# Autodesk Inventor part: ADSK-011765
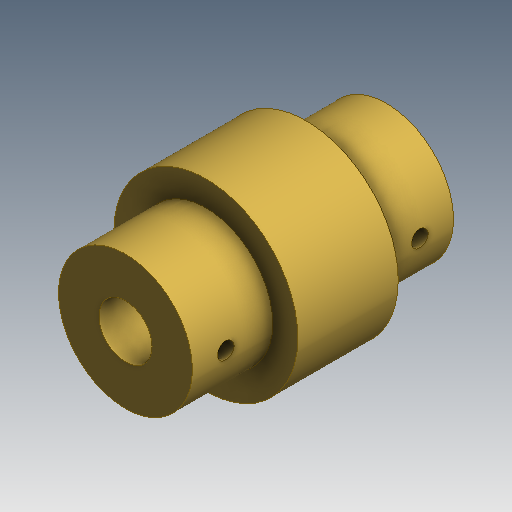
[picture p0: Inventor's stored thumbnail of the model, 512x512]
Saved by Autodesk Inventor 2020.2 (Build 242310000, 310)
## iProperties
Created: 1999-12
Part Number: ADSK-011765
Document SubType Name: Modeling
Designer: tgregory
Material: Générique
Density: 1 g/cm^3
Appearance: Vorgabe
Mass: 110.229 g
Surface Area: 210.674 cm^2
Volume: 110.229 cm^3
Control State: 0
Checked Out: False
Master: False
Shininess: 0.0
Length Units: 11272
Angle Units: 11279
Time Units: 11290
Mass Units: 11286
Length Display Precision: 3
Angle Display Precision: 2
Compacted: True
Dimensions: 2,2x3,1x2,2 in
Mass: 0,243 lb
VLT_Material: Generic
Density: 0.0
Volumn: 0.0
Area: 0.0
PropertySet Name: Model Information
Author: tgregory
Revision Number: -
Title: ADSK-011765
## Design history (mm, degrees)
node "Extrusion1" dims "d1" = 78.0034, "d2" = 0
node "Extrusion2" dims "d4" = 24.003, "d5" = 0
node "Extrusion3" dims "d7" = 24.003, "d8" = 0
node "Extrusion4" dims "d10" = 29.9974, "d11" = 0
node "Extrusion5" dims "d13" = 29.9974, "d14" = 0
node "Extrusion6" dims "d16" = 18.0086, "d17" = 0
workplane "Work Plane1"
node "Hole1" dims "d20" = 4.9784, "d21" = 9.525, "d22" = 6.35, "d23" = 60 deg, "d24" = 19.05, "d25" = 118 deg
node "Solide1"
node "Corps solides"
node "Corps surfaciques"
sketch "Sketch1"
  geometry: C1 r 27.495 at (0, 0)
  constraints: 1 centre point
  dimensions: "d0" = 54.991 diameter of C1
sketch "Sketch2"
  geometry: C1 r 27.495 at (0, 0) reference; C2 r 20.002 at (0, 0)
  constraints: 1 centre point, 1 coincident
  dimensions: "d3" = 40.005 diameter of C2
sketch "Sketch3"
  geometry: C1 r 27.495 at (0, 0) reference; C2 r 20.002 at (0, 0)
  constraints: 1 centre point, 1 coincident
  dimensions: "d6" = 40.005 diameter of C2
sketch "Sketch4"
  geometry: C1 r 20.002 at (0, 0) reference; C2 r 7.938 at (0, 0)
  constraints: 1 centre point, 1 coincident
  dimensions: "d9" = 15.875 diameter of C2
sketch "Sketch5"
  geometry: C1 r 20.002 at (0, 0) reference; C2 r 7 at (0, 0)
  constraints: 1 centre point, 1 coincident
  dimensions: "d12" = 14.00048 diameter of C2
sketch "Sketch6"
  geometry: C1 r 7 at (0, 0) reference; C2 r 13.5 at (0, 0)
  constraints: 1 centre point, 1 coincident
  dimensions: "d15" = 27.0002 diameter of C2
sketch "Sketch7"
  geometry: L1 (20.002, 0)-(-20.003, 0) reference; L2 (-20.003, -78.003)-(20.002, -78.003) reference; 2 further points
  dimensions: "d18" = 10.0076 distance from line of point (0, -10.008) L1; "d19" = 10.0076 distance from line of point (0, -67.996) L2 (= d18)
